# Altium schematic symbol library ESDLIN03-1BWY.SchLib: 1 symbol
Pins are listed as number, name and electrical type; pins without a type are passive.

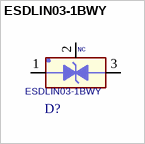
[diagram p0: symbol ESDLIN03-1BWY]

## ESDLIN03-1BWY
designator D?
footprint ST_SOT323-3L
pins: 1, 2 NC, 3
